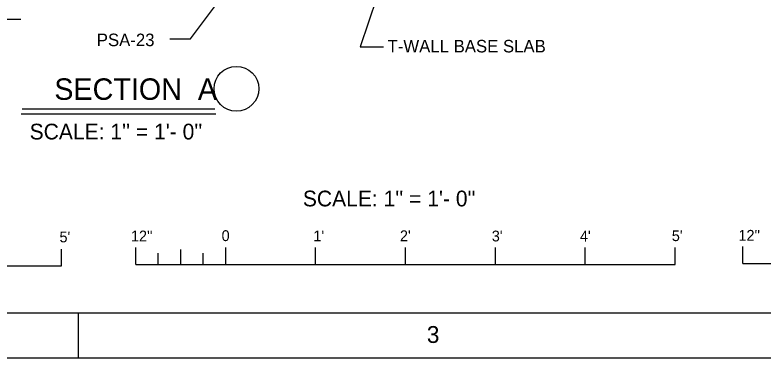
# Model space of a CAD drawing. Extents: x 22369.6 to 22428.3, y 22369.6 to 22415.
# Drawn here: x 22391.59 to 22402.68, y 22369.62 to 22374.71 of the extents above; entities that cross this region are included whole.
import ezdxf

# ---------------------------------------------------------------- set-up
doc = ezdxf.new("R2010")
doc.units = 0
for name, color, linetype in [('Level 1', 7, 'Continuous'), ('Level 10', 7, 'Continuous'), ('Level 2', 7, 'Continuous'), ('Level 3', 7, 'Continuous'), ('Level 4', 7, 'Continuous'), ('Level 7', 7, 'Continuous'), ('Level 9', 7, 'Continuous')]:
    doc.layers.add(name, color=color, linetype=linetype)

msp = doc.modelspace()

# ---------------------------------------------------------------- linework, layer by layer
at = {"layer": 'Level 1'}
for p, q in [((22394.191, 22374.351), (22395.228, 22375.742)), ((22397.078, 22375.334), (22396.705, 22374.236)), ((22393.884, 22374.351), (22394.191, 22374.351)), ((22396.705, 22374.236), (22397.055, 22374.236))]:
    msp.add_line(p, q, dxfattribs=at)
msp.add_lwpolyline([(22369.621, 22414.965), (22428.288, 22414.965), (22428.288, 22369.621), (22369.621, 22369.621)], close=True, dxfattribs=at)
at = {"layer": 'Level 10'}
for p, q in [((22389.306, 22374.646), (22391.676, 22374.646)), ((22391.678, 22373.24), (22394.567, 22373.24)), ((22391.693, 22373.313), (22394.552, 22373.313)), ((22392.528, 22369.621), (22392.528, 22370.293))]:
    msp.add_line(p, q, dxfattribs=at)
at = {"layer": 'Level 3'}
msp.add_circle((22394.872, 22373.612), 0.332, dxfattribs=at)
at = {"layer": 'Level 7'}
for p, q in [((22392.277, 22370.986), (22392.277, 22371.236)), ((22393.38, 22371.009), (22393.38, 22371.259)), ((22394.046, 22371.009), (22394.046, 22371.228)), ((22394.713, 22371.009), (22394.713, 22371.259)), ((22396.046, 22371.009), (22396.046, 22371.259)), ((22397.38, 22371.009), (22397.38, 22371.259)), ((22398.713, 22371.009), (22398.713, 22371.259)), ((22400.046, 22371.009), (22400.046, 22371.259)), ((22401.38, 22371.009), (22401.38, 22371.259)), ((22402.382, 22371.022), (22402.382, 22371.272)), ((22393.713, 22371.009), (22393.713, 22371.176)), ((22394.38, 22371.009), (22394.38, 22371.176)), ((22393.38, 22371.009), (22401.38, 22371.009)), ((22402.382, 22371.022), (22410.382, 22371.022)), ((22386.277, 22370.986), (22392.277, 22370.986))]:
    msp.add_line(p, q, dxfattribs=at)
at = {"layer": 'Level 9'}
msp.add_line((22371.621, 22370.293), (22423.952, 22370.293), dxfattribs=at)

# ---------------------------------------------------------------- texts
at = {"layer": 'Level 1'}
msp.add_text('3', height=0.25, dxfattribs=at).set_placement((22397.696, 22369.845))
at = {"layer": 'Level 2'}
for s, p in [("5'", (22392.248, 22371.336)), ("12''", (22393.308, 22371.35)), ('0', (22394.652, 22371.355)), ("1'", (22396.013, 22371.351)), ("2'", (22397.297, 22371.353)), ("3'", (22398.659, 22371.35)), ("4'", (22399.966, 22371.348)), ("5'", (22401.329, 22371.354)), ("12''", (22402.317, 22371.36))]:
    msp.add_text(s, height=0.16, dxfattribs=at).set_placement(p)
at = {"layer": 'Level 3'}
msp.add_text('SECTION  A', height=0.3184, dxfattribs=at).set_placement((22392.171, 22373.448))
at = {"layer": 'Level 4'}
for s, height, p in [('PSA-23', 0.1857, (22392.801, 22374.244)), ('T-WALL BASE SLAB', 0.18573, (22397.113, 22374.151))]:
    msp.add_text(s, height=height, dxfattribs=at).set_placement(p)
at = {"layer": 'Level 7'}
for p in [(22391.805, 22372.861), (22395.857, 22371.869)]:
    msp.add_text("SCALE: 1'' = 1'- 0''", height=0.23333, dxfattribs=at).set_placement(p)

doc.saveas('drawing.dxf')
